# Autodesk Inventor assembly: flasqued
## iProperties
Shininess: 21.0
Length Units: 11269
Angle Units: 11279
Time Units: 11290
Mass Units: 11283
Length Display Precision: 3
Angle Display Precision: 2
Compacted: True
Created: 2001-12
Part Number: flasqued
Document SubType Name: Assemblage
Designer: pichon
Density: 0.0
Volumn: 0.0
Area: 0.0
PropertySet Name: Model Information
Control State: 0
Master: False
Checked Out: False
Author: pichon
